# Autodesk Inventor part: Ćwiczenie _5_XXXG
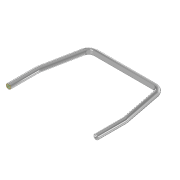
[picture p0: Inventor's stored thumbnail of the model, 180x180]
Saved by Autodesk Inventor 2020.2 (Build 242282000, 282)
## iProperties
Created: 2010-12
Part Number: Ćwiczenie _5_XXXG
Document SubType Name: Modelowanie
Designer: F.Stasiak
Density: 1 g/cm^3
Material: Ogólny
Appearance: Chrom — polerowany
Sheet Metal Rule: Domyślny
Manager: www.cadconsulting.pl
Company: Fabian Stasiak CAD Consulting
Author: F.Stasiak
Subject: Zbiór ćwiczeń. Autodesk Inventor 2020. Kurs podstawowy
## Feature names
1. Przeciągnięcie1
## Parameters: d4 = 35 mm, d6 = 3.5 mm, d11 = 0, Grubość = 0.5 mm, WspółczynnikK = 4.4 mm, PromieńGięcia = 0.5 mm, SzerokośćGięciaPodcięcia = 0.5 mm, GłębokośćGięciaPodcięcia = 0.25 mm, RozmiarPodcięciaNarożnika = 2 mm, OdstępPołączenia = 0.01 mm, MinimalnaPozostałość = 1 mm, PromieńPrzejścia = 0.5 mm, Rozmiar_promienia_Jacobiego = 0.5 mm, Wielk_odstępu = 0.5 mm, d16 = 0
